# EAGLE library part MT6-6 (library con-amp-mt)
AMP MT6 CONNECTOR
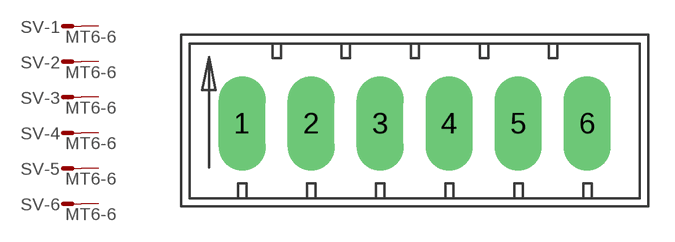
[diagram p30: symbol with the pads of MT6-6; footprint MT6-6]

Designator prefix SV; gates -1=MA -2=MA -3=MA -4=MA -5=MA -6=MA

## MT6-6 (OC_FARNELL: unknown; OC_NEWARK: unknown)  [MT6-6]
1  -1:S  pas
2  -2:S  pas
3  -3:S  pas
4  -4:S  pas
5  -5:S  pas
6  -6:S  pas

## Footprint MT6-6 (pad centres in mm)
AMP MT6 CONNECTOR
drill 1.803 long: 1 -9.906,0; 2 -5.944,0; 3 -1.981,0; 4 1.981,0; 5 5.944,0; 6 9.906,0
